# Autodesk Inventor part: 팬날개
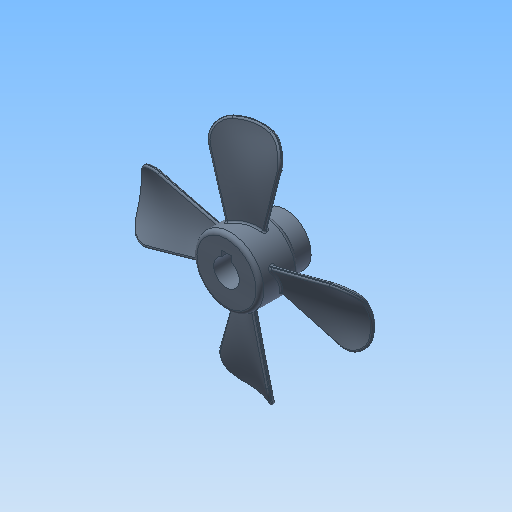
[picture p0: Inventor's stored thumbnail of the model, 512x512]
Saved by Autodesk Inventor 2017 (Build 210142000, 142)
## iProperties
Company: 한국ATC센터
Created: 2016-06
Part Number: 팬날개
Document SubType Name: Modeling
Designer: mdu
Density: 1.06 g/cm^3
Material: ABS 플라스틱
Mass: 29.2536 g
Surface Area: 148.135 cm^2
Volume: 27.5977 cm^3
Appearance: 강청색
Author: mdu
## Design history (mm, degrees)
sketch "스케치1"
  geometry: L1 (-15, 0)-(15, 0); L2 (-15, 0)-(-15, 17); L3 (-15, 17)-(5, 17); L4 (5, 17)-(5, 13); L5 (5, 13)-(15, 13); L6 (15, 13)-(15, 0); 2 further points
  constraints: 12 end point, 3 parallel, 2 perpendicular, 1 coincident, 1 horizontal, 1 midpoint
  dimensions: "d0" = 30 distance of L1.start L1.end; "d8" = 34 diameter of L3 L1; "d10" = 26 diameter of L5 L1; "d32" = 20 distance of L2.end L3.end
revolve "회전1" sketch "스케치1" stored, may be unused: angle "d11" = 90 deg
node "작업 평면2"
sketch "스케치7"
  geometry: L1 (-15, 17)-(5, 17) reference; L2 (-15, -17)-(5, -17) reference; L3 (-5, 17)-(-5, -17); A1 r 35 centre (-36.399, -13.457) between (-2, -7) and (-8, 7); 1 further point
  constraints: 2 end point, 2 midpoint, 2 point on circle, 1 centre point
  dimensions: "d36" = 35 radius of A1; "d37" = 10 distance from line of A1.start L2; "d38" = 10 distance from line of A1.end L1; "d45" = 3 distance from line of A1.end L3; "d46" = 3 distance from line of A1.start L3
sketch "3D 스케치1"
  geometry: L1 through (0, 0) direction (1, 0) reference; L2 through (0, 0) direction (1, 0) reference; 13 other entities
  constraints: 2 collinear
  node "투영 원본 위치 스케치7"
sketch "스케치8"
  geometry: L1 (-15, 17)-(5, 17) reference; L2 (-15, -17)-(5, -17) reference; L3 (-5, 17)-(-5, -17); A1 r 30 centre (-28.74, -3.591) between (-3, -19) and (-9, 19); 1 further point
  constraints: 2 end point, 2 midpoint, 2 point on circle, 1 centre point
  dimensions: "d43" = 30 radius of A1; "d47" = 4 distance from line of A1.end L3; "d48" = 2 distance from line of A1.start L3; "d58" = 2 distance from line of A1.end L1; "d59" = 2 distance from line of A1.start L2
sketch "3D 스케치2"
sketch "3D 스케치3"
feature "경계 패치1" sketch "3D 스케치2", "3D 스케치3" dims "d50" = 0
feature "연장1" dims "d55" = 2
feature "두껍게 하기1" dims "d51" = 2, "d52" = 2
sketch "스케치9"
  geometry: C1 r 59 at (0, 0); 1 further point
  constraints: 1 centre point, 1 coincident
  dimensions: "d60" = 118 diameter of C1
extrude "돌출2" sketch "스케치9" distance "d62" = 200; taper "d63" = 0 deg
fillet "모깎기6" dims "d64" = 10
fillet "모깎기7" dims "d66" = 0.8
fillet "모깎기8" dims "d67" = 0.8
sketch "스케치2"
  geometry: L1 (-2.5, 6)-(-2.5, 8.8); L2 (-2.5, 8.8)-(2.5, 8.8); L3 (2.5, 8.8)-(2.5, 6); A1 r 6.5 centre (0, 0) between (-2.5, 6) and (2.5, 6); 1 further point
  constraints: 6 end point, 2 parallel, 2 point on circle, 1 centre point, 1 coincident, 1 horizontal, 1 vertical
  dimensions: "d12" = 13 diameter of A1; "d13" = 5 distance of L1.end L2.end; "d14" = 15.3 dimension on A1 L2 (computed from d12)
extrude "돌출1" cut sketch "스케치2" stored distance "d15" = 10; taper "d16" = 0 deg
chamfer "모따기1" distance "d17" = 1; stored, may be unused: second distance "d18" = 2, angle "d19" = 45 deg
node "작업 평면1"
sketch "스케치3"
  geometry: L1 (5, -13)-(5, 13) reference; 3 further points
  constraints: 1 horizontal alignment, 1 midpoint
  dimensions: "d20" = 5 distance from line of L1 point (0, 0)
hole "구멍1" sketch "스케치3" at (0, 0) diameter "d21" = 2.459; stored, may be unused: countersink angle "d25" = 90 deg, drill point angle "d27" = 118 deg; dims "d22" = 6, "d23" = 4, "d24" = 2, "d26" = 8
fillet "모깎기9" dims "d77" = 2
fillet "모깎기10" dims "d78" = 2
fillet "모깎기11" dims "d79" = 2
node "솔리드1"
pattern_circular "원형 패턴1" dims angle "d69" = 360 deg
pattern_circular "원형 패턴2" dims angle "d72" = 360 deg
pattern_circular "원형 패턴3" dims angle "d75" = 360 deg
node "투영 원본 위치 스케치8"
node "곡면1"
node "곡면2"
node "곡면3"
node "곡면4"
feature "경계 패치2"
feature "경계 패치3"
feature "경계 패치4"
